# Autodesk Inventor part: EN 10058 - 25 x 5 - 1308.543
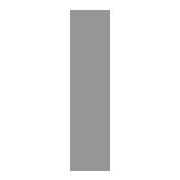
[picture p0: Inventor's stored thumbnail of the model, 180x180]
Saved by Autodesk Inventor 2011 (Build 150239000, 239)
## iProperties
Created: 2010-02
Part Number: EN 10058 - 25 x 5 - 1308.543
Material: Steel, Mild
Description: flat steel bar 25*5
Document SubType Name: Modeling
Standard: DIN
Designer: PC
Standard Revision: 2004
Standards Organization: DIN
Language: en-US
Size Designation: 25 x 5
Categories: <MemberInstance><Categories><Category DisplayName="Structural Shapes" InternalName="089c4875-fa83-4c05-b084-43b9cc11f5ed" Mnemonic="GRDR"><CategoryParameter Dis
Stock Number: 25 x 5
Density: 7.86 g/cm^3
Mass: 1285.64 g
Surface Area: 787.626 cm^2
Volume: 163.568 cm^3
_CCFamilyMember: 18
_CCFamilyDisplayName: DIN EN 10058 - Hot rolled flat steel bars for general purposes
_FrameMemberDoc: Frame Member File
_Version: 15.0.0
_GetPNFromCC: 1
IsCustomPart: 1
G_L: 1308.543 mm
G_W: 5.000 mm
G_H: 25.000 mm
Author: PC
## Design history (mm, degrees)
node "Start plane"
node "End plane"
sketch "Sketch"
  geometry: L1 (2.5, -12.5)-(-2.5, -12.5); L2 (-2.5, -12.5)-(-2.5, 12.5); L3 (-2.5, 12.5)-(2.5, 12.5); L4 (2.5, 12.5)-(2.5, -12.5); L5 (-6, 0)-(8, 0); L6 (0, -30)-(0, 40); L7 (0, 54)-(0, -44) reference; L8 (-9.2, 0)-(13.2, 0) reference
  constraints: 12 end point, 2 collinear, 2 parallel, 1 horizontal, 1 perpendicular
  dimensions: "d0" = 25 distance between parallel lines of L3 L1 (= G_W); "d1" = 5 distance between parallel lines of L4 L2 (= G_H); "d4" = 2.5 distance between parallel lines of L6 L4 (= 0.5 x d1); "d5" = 12.5 distance between parallel lines of L5 L3 (= 0.5 x d0)
extrude "Body" new body sketch "Sketch" stored distance "d2" = 1308.54288 (= G_L); taper "d3" = 0 deg
node "Driven Length"
  sketch "Sketch3"
    geometry: L1 (0, 0)-(10, 0) reference
    constraints: 2 end point, 1 horizontal
  workplane "Work Plane3"
  sketch "Sketch4"
    geometry: L1 (-2, 0)-(12, 0) reference; L2 (-2, 1308.543)-(12, 1308.543) reference
    dimensions: "d9" = 1308.54288 distance between parallel lines of L1 L2 (derived)
body "Solid1"
other parameters: "G_W" = 25 [user parameter; used in 1 equation term], "G_H" = 5 [user parameter; used in 1 equation term], "G_L" = 1308.54288 (= d9) [user parameter; used in 1 equation term], "G_OFFSET_START" = 0 [user parameter; used in 1 equation term], "G_OFFSET_END" = 0 [user parameter; used in 1 equation term], "d6" = 0 (computed from G_OFFSET_START), "d7" = 1308.54288 (= G_OFFSET_END + B_L), "B_L" = 1308.54288 [user parameter; used in 1 equation term], "d8" = 90 deg, "MAS" = 0.0981 [user parameter]
